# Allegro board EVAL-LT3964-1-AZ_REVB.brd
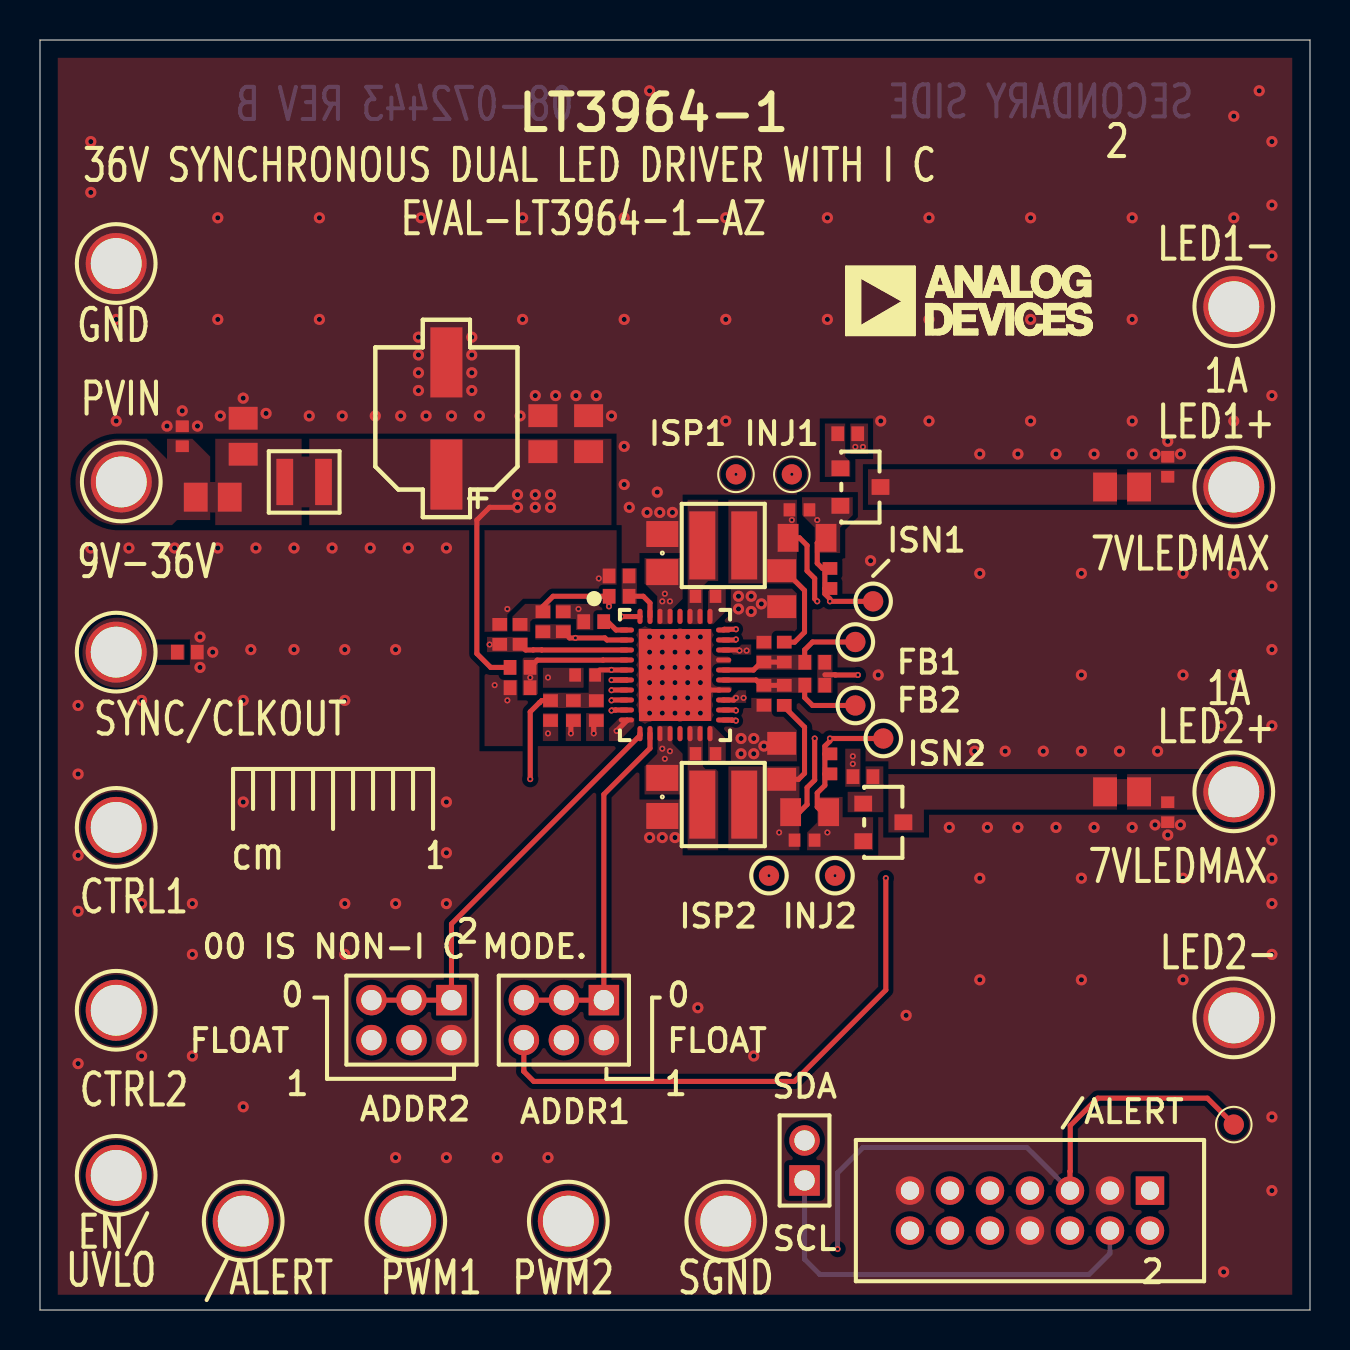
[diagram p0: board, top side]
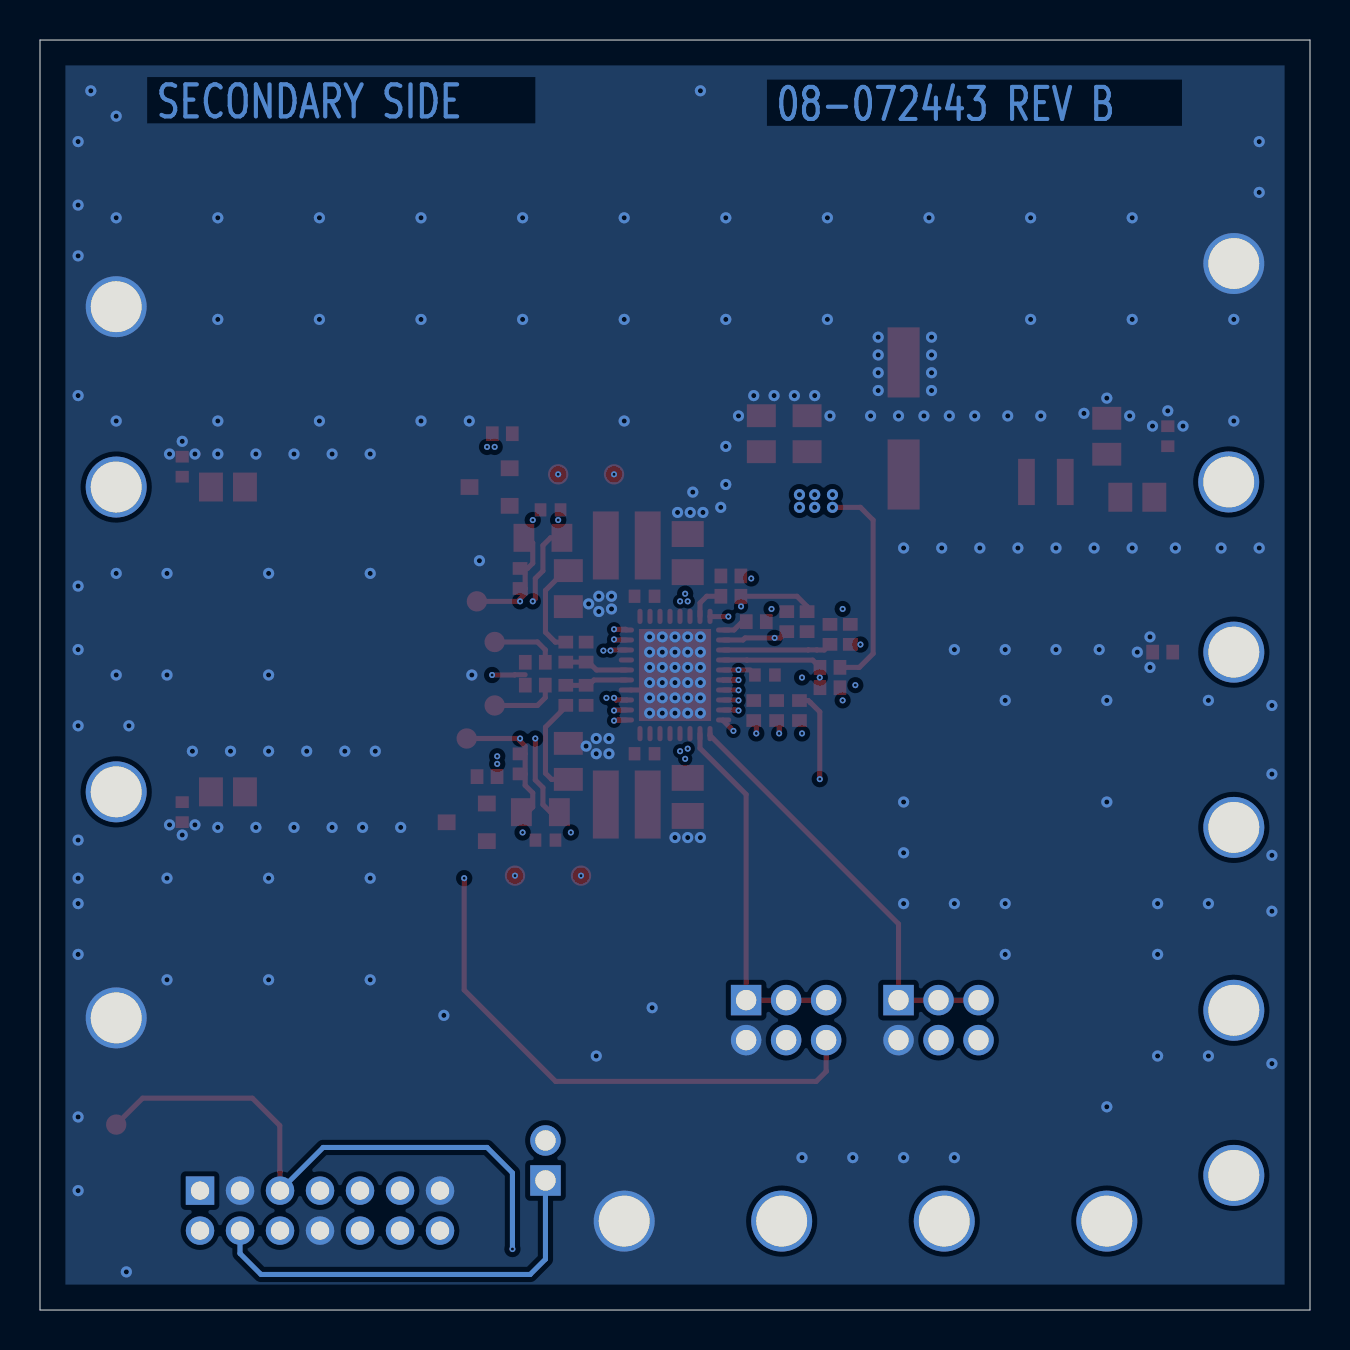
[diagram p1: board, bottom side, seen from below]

Outline 63.5 x 63.5 mm; copper layers: TOP, LAYER2, LAYER3, BOTTOM. Coordinates in mm from the lower left corner of the outline.
Outline path: 0,63.5 63.5,63.5 63.5,0 0,0 0,63.5

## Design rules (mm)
constraint set DEFAULT: min track width 0.254

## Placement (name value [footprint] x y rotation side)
C1  2.2uF  [C0805H60]  31.11 37.85 90 top
C2  TBD0402  [C0402]  37.97 40.01 0 top
C3  TBD0805  [C0805]  27.43 43.81 90 top
C4  TBD0805  [C0805]  25.15 43.81 90 top
C5  33UF  [CPLSMSQ260H303]  20.32 44.58 90 top
C6  2.2UF  [C0402]  27.25 31.75 180 top
C7  2.2uF  [C0805H60]  31.11 25.65 270 top
C8  TBD0402  [C0402]  38.23 23.49 0 top
C9  0.22uF  [C0402]  33.27 35.69 180 top
C10  2.2uF  [C0805]  37.08 36.07 270 top
C11  0.22uF  [C0402]  33.27 27.81 180 top
C12  2.2uF  [C0805]  37.08 27.43 90 top
C13  TBD0402  [C0402]  7.11 43.69 90 top
C14  TBD0805  [C0805]  10.16 43.69 90 top
C18  TBD0402  [C0402]  56.39 42.16 90 top
C19  TBD0402  [C0402]  56.39 24.89 270 top
E1  2501-2-00-80-00-00-07-0  [CNMILLMAX2501]  4.06 41.4 0 top
E2  2501-2-00-80-00-00-07-0  [CNMILLMAX2501]  3.81 52.32 0 top
E3  2501-2-00-80-00-00-07-0  [CNMILLMAX2501]  59.69 41.15 0 top
E4  2501-2-00-80-00-00-07-0  [CNMILLMAX2501]  59.69 50.16 0 top
E5  2501-2-00-80-00-00-07-0  [CNMILLMAX2501]  59.69 25.91 0 top
E6  2501-2-00-80-00-00-07-0  [CNMILLMAX2501]  59.69 14.61 0 top
E7  2501-2-00-80-00-00-07-0  [CNMILLMAX2501]  3.81 6.73 0 top
E8  2501-2-00-80-00-00-07-0  [CNMILLMAX2501]  3.81 24.13 0 top
E9  2501-2-00-80-00-00-07-0  [CNMILLMAX2501]  3.81 14.99 0 top
E10  2501-2-00-80-00-00-07-0  [CNMILLMAX2501]  10.16 4.45 0 top
E11  2501-2-00-80-00-00-07-0  [CNMILLMAX2501]  3.81 32.89 0 top
E12  2501-2-00-80-00-00-07-0  [CNMILLMAX2501]  18.29 4.45 0 top
E13  2501-2-00-80-00-00-07-0  [CNMILLMAX2501]  26.42 4.45 0 top
E14  2501-2-00-80-00-00-07-0  [CNMILLMAX2501]  34.29 4.45 0 top
FB1  100OHM  [L0805]  8.64 40.64 180 top
FB2  1500 OHMS  [L0805]  54.1 41.15 0 top
FB3  1500 OHMS  [L0805]  54.1 25.91 0 top
J1  87831-1420  [CNMOLEX87831-1420]  55.5 5.97 180 top
JP1  TMM-103-02-L-D  [CNTHMHDR2X3L236W155H225]  28.19 15.49 180 top
JP2  TMM-103-02-L-D  [CNTHMHDR2X3L236W155H225]  20.57 15.49 180 top
JP3  TMM-102-01-G-S  [CNHDR1X2H195]  38.23 6.48 90 top
L1  4.7UH  [LSMSQ118H79_A]  34.16 38.23 0 top
L2  4.7UH  [LSMSQ118H79_A]  34.16 25.27 0 top
L3  2.2UH  [LSML98W79H39]  13.21 41.4 0 top
M1  IRLML6401TRPBF  [SOT23-M3]  41.02 41.15 270 top
M2  IRLML6401TRPBF  [SOT23-M3]  42.16 24.38 270 top
NOREF  -  []  316.99 177.42 0 top
NOREF#2  -  []  -165.35 -246.38 0 top
NOREF#3  -  []  -165.35 -246.38 0 top
NOREF#4  -  []  321.44 105.79 0 top
NOREF#5  -  []  0.64 62.86 270 top
NOREF#6  -  []  32.26 75.95 0 top
NOREF#7  -  []  -41.2 219.96 0 top
NOREF#8  -  []  104.85 72.6 0 top
NOREF#9  -  []  62.86 0.64 90 top
NOREF#10  -  []  0 0 90 top
NOREF#11  -  []  0.64 0.64 0 top
NOREF#12  -  []  62.86 62.86 180 top
NOREF#13  -  []  -165.35 -246.38 0 top
NOREF#14  -  []  -162.05 -236.73 0 top
NOREF#15  -  []  0 63.5 0 top
NOREF#16  -  []  9.65 27.05 0 top
NOREF#17  -  []  41.4 69.98 0 top
R1  332K  [R0402]  24 32.13 0 top
R2  51.1K  [R0402]  24 31.11 0 top
R3  100K  [R0402]  25.53 29.97 270 top
R4  100K  [R0402]  25.15 34.42 90 top
R5  100K  [R0402]  24 33.78 90 top
R6  165K  [R0402]  28.96 35.69 180 top
R7  499K  [R0402]  28.96 36.7 0 top
R8  27.4K  [R0402]  27.69 34.42 0 top
R9  20K  [R0402]  7.37 32.89 180 top
R10  1MEG  [R0402]  37.21 32.89 270 top
R11  169K  [R0402]  36.2 32.89 90 top
R12  0.1  [R0805]  38.35 38.61 0 top
R13  TBD0402  [R0402]  39.5 36.58 90 top
R14  1MEG  [R0402]  37.21 30.73 90 top
R15  169K  [R0402]  36.2 30.73 270 top
R16  0.1  [R0805]  38.48 24.89 0 top
R17  TBD0402  [R0402]  39.5 27.3 270 top
R21  TBD0402  [R0402]  22.99 33.78 270 top
R22  TBD0402  [R0402]  26.16 34.42 270 top
R24  TBD0402  [R0402]  38.73 32.38 180 top
R25  TBD0402  [R0402]  38.73 31.24 180 top
R26  100K  [R0402]  26.67 29.97 270 top
R27  100K  [R0402]  27.81 29.97 270 top
R28  0  [R0402]  40.39 43.81 180 top
R29  0  [R0402]  41.15 26.67 0 top
TP1  TESTPAD  [TPSMC40]  42.16 28.57 0 top
TP2  TESTPAD  [TPSMC40]  59.69 9.27 0 top
TP5  TESTPAD  [TPSMC40]  40.77 33.4 0 top
TP6  TESTPAD  [TPSMC40]  37.59 41.78 0 top
TP7  TESTPAD  [TPSMC40]  41.66 35.43 0 top
TP8  TESTPAD  [TPSMC40]  34.8 41.78 0 top
TP9  TESTPAD  [TPSMC40]  36.45 21.72 0 top
TP10  TESTPAD  [TPSMC40]  39.75 21.72 0 top
TP11  TESTPAD  [TPSMC40]  40.77 30.23 0 top
U1  LT3964RUHE-1#PBF  [QFN36_5X6_PAD4_6X3_6-05-08-1876]  31.75 31.75 270 top

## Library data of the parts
C1 C7 = CAP: Tolerance: 10; User Part Number: UPN; alternate symbols: (C0805H60); part number: CAP_SM-2.2UF,50V,10,E016729,C0805H60; tolerance: 10
C2 C8 C13 C18 C19 = CAP: User Part Number: UPN; alternate symbols: (C0402); part number: CAP_SM-TBD0402,TBD0402,TBD0402,E000381,C0402
C3 C4 C14 = CAP: User Part Number: UPN; alternate symbols: (C0805); part number: CAP_SM-TBD0805,TBD0805,TBD0805,E000383,C0805
C5 = CAPP: User Part Number: UPN; Tolerance: 20; alternate symbols: (CPLSMSQ260H303); part number: CAPP_SM-33UF,50V,20,E058112,CPLSMSQ260H303; tolerance: 20
C6 = CAP: User Part Number: UPN; Tolerance: 10; alternate symbols: (C0402); part number: CAP_SM-2.2UF,25V,10,E044855,C0402; tolerance: 10
C9 C11 = CAP: User Part Number: UPN; Tolerance: 10; alternate symbols: (C0402); part number: CAP_SM-0.22UF,50V,10,E038241,C0402; tolerance: 10
C10 C12 = CAP: User Part Number: UPN; Tolerance: 10; alternate symbols: (C0805); part number: CAP_SM-2.2UF,10V,10,E010425,C0805; tolerance: 10
E1-E14 = CNTP1P: User Part Number: UPN; Tolerance: N/A; alternate symbols: (CNMILLMAX2501); part number: CNTP1P_TH-2501-2-00-80-00-00-07-0,E031108,CNMILLMAX2501; tolerance: N/A
FB1 = FERRITE: User Part Number: UPN; Tolerance: 25; alternate symbols: (L0805); part number: FERRITE_SM-100OHM,25,E012241,L0805; tolerance: 25
FB2 FB3 = FERRITE: User Part Number: UPN; Tolerance: 25; alternate symbols: (L0805); part number: FERRITE_SM-1500 OHMS,25,E008092,L0805; tolerance: 25
J1 = CN14P: Tolerance: N/A; User Part Number: UPN; alternate symbols: (CNMOLEX87831-1420); part number: CN14P_TH-87831-1420,E010086,CNMOLEX87831-1420; tolerance: N/A
JP1 JP2 = CN6P_ODD_EVEN: User Part Number: UPN; Tolerance: N/A; alternate symbols: (CNTHMHDR2X3L236W155H225); part number: CN6P_ODD_EVEN_TH-TMM-103-02-L-D,E043044,CNTHMHDR2X3L236W155H225; tolerance: N/A
JP3 = CN2P: Tolerance: N/A; User Part Number: UPN; alternate symbols: (CNHDR1X2H195); part number: CN2P_TH-TMM-102-01-G-S,E021460,CNHDR1X2H195; tolerance: N/A
L1 L2 = IND: User Part Number: UPN; Tolerance: 20; alternate symbols: (LSMSQ118H79_A); part number: IND_SM-4.7UH,20,E024887,LSMSQ118H79_A; tolerance: 20
L3 = IND: User Part Number: UPN; Tolerance: 20; alternate symbols: (LSML98W79H39); part number: IND_SM-2.2UH,20,E058020,LSML98W79H39; tolerance: 20
M1 M2 = TRANPMOSFET_V12: User Part Number: UPN; Tolerance: N/A; alternate symbols: (SOT23-M3); part number: TRANPMOSFET_V12_SM-IRLML6401TRPBF,E023655,SOT23-M3; tolerance: N/A
R1 = RES: User Part Number: UPN; Tolerance: 1; alternate symbols: (R0402); part number: RES_SM-332K,E003766,1/10W,1,R0402; tolerance: 1
R2 = RES: User Part Number: UPN; Tolerance: 0.1; alternate symbols: (R0402); part number: RES_SM-51.1K,E020550,1/16W,0.1,R0402; tolerance: 0.1
R3-R5 R26 R27 = RES: User Part Number: UPN; Tolerance: 1; alternate symbols: (R0402); part number: RES_SM-100K,E017855,1/16W,1,R0402; tolerance: 1
R6 = RES: User Part Number: UPN; Tolerance: 1; alternate symbols: (R0402); part number: RES_SM-165K,E026053,1/16W,1,R0402; tolerance: 1
R7 = RES: User Part Number: UPN; Tolerance: 1; alternate symbols: (R0402); part number: RES_SM-499K,E019889,1/10W,1,R0402; tolerance: 1
R8 = RES: User Part Number: UPN; Tolerance: 1; alternate symbols: (R0402); part number: RES_SM-27.4K,E021819,1/10W,1,R0402; tolerance: 1
R9 = RES: User Part Number: UPN; Tolerance: 1; alternate symbols: (R0402); part number: RES_SM-20K,E003791,1/10W,1,R0402; tolerance: 1
R10 R14 = RES: User Part Number: UPN; Tolerance: 1; alternate symbols: (R0402); part number: RES_SM-1MEG,E003749,1/10W,1,R0402; tolerance: 1
R11 R15 = RES: User Part Number: UPN; Tolerance: 1; alternate symbols: (R0402); part number: RES_SM-169K,E006751,1/10W,1,R0402; tolerance: 1
R12 R16 = RES: User Part Number: UPN; Tolerance: 1; alternate symbols: (R0805); part number: RES_SM-0.1,E031559,1/2W,1,R0805; tolerance: 1
R13 R17 R21 R22 R24 R25 = RES: User Part Number: UPN; alternate symbols: (R0402); part number: RES_SM-TBD0402,E004049,TBD0402,TBD0402,R0402
R28 R29 = RES: User Part Number: UPN; Tolerance: JUMPER; alternate symbols: (R0402); part number: RES_SM-0,E003438,1/10W,JUMPER,R0402; tolerance: JUMPER
TP1 TP2 TP5-TP11 = NCTESTPAD: Tolerance: N/A; User Part Number: UPN; alternate symbols: (TPSMC40); part number: NCTESTPAD_SM-TESTPAD,E019801,TPSMC40; tolerance: N/A
U1 = ADLT3964_1: Tolerance: N/A; User Part Number: UPN; alternate symbols: (QFN36_5X6_PAD4_6X3_6-05-08-1876); part number: ADLT3964_1_SM-LT3964RUHE-1#PBF,E058111,QFN36_5X6_PAD4_6X3_6-05-08-1876; tolerance: N/A

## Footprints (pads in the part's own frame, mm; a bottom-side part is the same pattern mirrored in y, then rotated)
C0402
  rect 0.584x0.66 smd: 1(-0.5,0) 2(0.5,0)
C0805
  rect 1.143x1.448 smd: 1(-0.9,0) 2(0.9,0)
C0805H60
  rect 1.295x1.6 smd: 1(-0.953,0) 2(0.953,0)
CNHDR1X2H195
  rect 1.524x1.524 hole 1.016: 1(0,0)
  round 1.524 hole 1.016: 2(1.999,0)
CNMILLMAX2501
  round 3.048 hole 2.54: 1(0,0)
CNMOLEX87831-1420
  rect 1.422x1.422 hole 0.914: 1(0,0)
  round 1.422 hole 0.914: 2(0,2) 3(2,0) 4(2,2) 5(4,0) 6(4,2) 7(6,0) 8(6,2) 9(8,0) 10(8,2) 11(10,0) 12(10,2) 13(12,0) 14(12,2)
CNTHMHDR2X3L236W155H225
  rect 1.524x1.524 hole 1.016: 1(0,0)
  round 1.524 hole 1.016: 2(0,2) 3(2,0) 4(2,2) 5(4,0) 6(4,2)
CPLSMSQ260H303
  rect 3.505x1.6 smd: N(2.803,0) P(-2.803,0)
L0805
  rect 1.194x1.448 smd: 1(-0.85,0) 2(0.85,0)
LSML98W79H39
  rect 0.838x2.311 smd: 1(-0.969,0) 2(0.969,0)
LSMSQ118H79_A
  rect 1.295x3.404 smd: 1(-1.048,0) 2(1.048,0)
QFN36_5X6_PAD4_6X3_6-05-08-1876
  oval 0.254x0.762 smd: 1(-2.25,-2.431) 2(-1.75,-2.431) 3(-1.25,-2.431) 4(-0.75,-2.431) 5(-0.25,-2.431) 6(0.25,-2.431) 7(0.75,-2.431) 8(1.25,-2.431) 9(1.75,-2.431) 10(2.25,-2.431) 19(2.25,2.431) 20(1.75,2.431) 21(1.25,2.431) 22(0.75,2.431) 23(0.25,2.431) 24(-0.25,2.431) 25(-0.75,2.431) 26(-1.25,2.431) 27(-1.75,2.431) 28(-2.25,2.431)
  oval 0.762x0.254 smd: 11(2.931,-1.75) 12(2.931,-1.25) 13(2.931,-0.75) 14(2.931,-0.25) 15(2.931,0.25) 16(2.931,0.75) 17(2.931,1.25) 18(2.931,1.75) 29(-2.931,1.75) 30(-2.931,1.25) 31(-2.931,0.75) 32(-2.931,0.25) 33(-2.931,-0.25) 34(-2.931,-0.75) 35(-2.931,-1.25) 36(-2.931,-1.75)
  rect 4.597x3.607 smd: 37(0,0)
R0402
  rect 0.635x0.737 smd: 1(-0.5,0) 2(0.5,0)
R0805
  rect 1.041x1.397 smd: 1(-0.95,0) 2(0.95,0)
SOT23-M3
  rect 0.787x0.889 smd: 1(-0.94,-1.003) 2(0.94,-1.003) 3(0,1.003)
TPSMC40
  round 1.016 smd: 1(0,0)

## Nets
GND_POWER: C1.2(N2) C3.2(N2) C4.2(N2) C5.N(N2) C6.2(N2) C7.2(N2) C10.2(N2) C12.2(N2) C13.2(N2) C14.2(N2) C18.2(N2) C19.2(N2) E2.1(N1) E4.1(N1) E6.1(N1) E14.1(N1) J1.3 J1.8 J1.13 JP1.2 JP2.2 R2.1 R7.1 R8.1 R9.1 R11.2(N2) R15.2(N2) R21.1 R22.1 U1.22 U1.25 U1.37
VIN: C1.1 C3.1 C4.1 C5.P C7.1 C13.1 C14.1 E1.1(N1) FB1.1 FB1.2(N2) L3.1 L3.2(N2) R1.1 U1.13 U1.14(VIN2_2) U1.33 U1.34
ALERT: E10.1(N1) J1.5 R3.2(N2) TP2.1(N1) U1.6
INTVCC: C6.1 JP1.6(N6) JP2.6(N6) R3.1 R4.2(N2) R5.2(N2) R6.2(N2) R24.1 R25.1 R26.1 R27.1 U1.5
SCL: J1.4 JP3.1 U1.10
SDA: J1.7 JP3.2(N2) U1.9
UNNAMED_3_ADLT39641_I220_ADDR1: JP1.1 JP1.3 JP1.5 U1.12
UNNAMED_3_ADLT39641_I220_ADDR2: JP2.1 JP2.3 JP2.5 U1.11
UNNAMED_3_ADLT39641_I220_BST1: C9.1 U1.29
UNNAMED_3_ADLT39641_I220_BST2: C11.1 U1.18
UNNAMED_3_ADLT39641_I220_FB1: R10.2(N2) R11.1 R24.2(N2) TP5.1(N1) U1.24
UNNAMED_3_ADLT39641_I220_FB2: R14.2(N2) R15.1 R25.2(N2) TP11.1(N1) U1.23
UNNAMED_3_ADLT39641_I220_ISN1: C2.2(N2) M1.2(S) R12.2(N2) R13.1 R13.2(N2) TP6.1(N1) TP7.1(N1) U1.27
UNNAMED_3_ADLT39641_I220_ISP1: C2.1 C10.1 L1.2(N2) R10.1 R12.1 TP8.1(N1) U1.28
UNNAMED_3_ADLT39641_I220_PWM2: E13.1(N1) R27.2(N2) U1.8
UNNAMED_3_ADLT39641_I220_PWMTG1: R28.1 U1.26
UNNAMED_3_ADLT39641_I220_PWMTG2: R29.1 U1.21
UNNAMED_3_ADLT39641_I220_RT: R8.2(N2) U1.1
UNNAMED_3_ADLT39641_I220_SW11: C9.2(N2) L1.1 U1.30 U1.31
UNNAMED_3_ADLT39641_I220_SW21: C11.2(N2) L2.1 U1.16 U1.17
UNNAMED_3_ADLT39641_I220_TSET: R6.1 R7.2(N2) U1.35
UNNAMED_3_CAP_I157_N1: C18.1 E3.1(N1) FB2.1 FB2.2(N2) M1.3
UNNAMED_3_CAP_I172_N1: C19.1 E5.1(N1) FB3.1 FB3.2(N2) M2.3
UNNAMED_3_CAP_I178_N1: C8.1 C12.1 L2.2(N2) R14.1 R16.1 TP9.1(N1) U1.19
UNNAMED_3_CAP_I178_N2: C8.2(N2) M2.2(S) R16.2(N2) R17.1 R17.2(N2) TP1.1(N1) TP10.1(N1) U1.20
UNNAMED_3_CNTP1P_I106_N1: E7.1(N1) R1.2(N2) R2.2(N2) U1.4
UNNAMED_3_CNTP1P_I107_N1: E8.1(N1) R4.1 R22.2(N2) U1.2
UNNAMED_3_CNTP1P_I108_N1: E9.1(N1) R5.1 R21.2(N2) U1.3
UNNAMED_3_CNTP1P_I124_N1: E11.1(N1) R9.2(N2) U1.36
UNNAMED_3_CNTP1P_I125_N1: E12.1(N1) R26.2(N2) U1.7
UNNAMED_3_RES_I210_N2: M1.1 R28.2(N2)
UNNAMED_3_RES_I215_N2: M2.1 R29.2(N2)

Pads without a net: J1 1 2 6 9 10 11 12 14; JP1 4; JP2 4; U1 15 32

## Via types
v1: diameter 0.305, hole 0.152, TOP to BOTTOM, 54 vias
v2: diameter 0.559, hole 0.254, TOP to BOTTOM, 214 vias

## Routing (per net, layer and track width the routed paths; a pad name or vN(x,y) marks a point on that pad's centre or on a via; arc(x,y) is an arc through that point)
GND_POWER: length 2.4
  TOP w0.254: v2(33.02,30.61) 33.02,31 33.96,31 ; v2(33.02,33.66) 33.08,33.66 33.08,32.66
  vias: v1(22.73,31.24) v1(23.37,35.05) v1(23.37,30.48) v1(25.4,31.62) v1(26.92,35.05) v1(27.94,36.58) v2(1.91,30.23) v2(1.91,26.8) v2(1.91,22.73) v2(1.91,19.94) v2(1.91,12.32) v2(2.54,58.42) v2(2.54,55.88) v2(2.54,38.1) v2(3.81,49.53) v2(3.81,44.45) v2(4.45,38.1) v2(5.08,30.48) v2(5.08,20.32) v2(5.08,12.7) v2(6.35,44.2) v2(6.73,38.1) v2(7.11,44.96) v2(7.62,20.32) v2(7.62,17.78) v2(7.62,12.7) v2(7.87,44.2) v2(8,33.66) v2(8,32.13) v2(8.64,32.89) v2(8.89,54.61) v2(8.89,49.53) v2(8.89,38.1) v2(9.02,44.7) v2(10.16,45.59) v2(10.16,30.48) v2(10.16,25.4) v2(10.16,10.16) v2(10.54,33.02) v2(10.8,38.1) v2(11.3,44.83) v2(12.7,38.1) v2(12.7,33.02) v2(13.46,44.7) v2(13.97,54.61) v2(13.97,49.53) v2(14.61,38.1) v2(15.11,44.7) v2(15.24,33.02) v2(15.24,30.48) v2(15.24,20.32) v2(15.24,17.78) v2(16.51,38.1) v2(16.76,44.7) v2(17.78,33.02) v2(17.78,20.32) v2(17.78,7.62) v2(18.03,44.7) v2(18.41,38.1) v2(18.92,48.64) v2(18.92,47.75) v2(18.92,46.86) v2(18.92,45.97) v2(19.05,54.61) v2(19.3,44.7) v2(20.32,38.1) v2(20.32,25.4) v2(20.32,22.86) v2(20.32,20.32) v2(20.32,7.62) v2(20.57,44.7) v2(21.59,48.64) v2(21.59,47.75) v2(21.59,46.86) v2(21.59,45.97) v2(21.97,44.7) v2(22.86,7.62) v2(24,44.7) v2(24.13,54.61) v2(24.13,49.53) v2(24.77,45.72) v2(25.4,7.62) v2(25.78,45.72) v2(26.8,45.72) v2(27.81,45.72) v2(28.57,44.7) v2(29.21,54.61) v2(29.21,49.53) v2(29.21,43.18) v2(29.21,41.27) v2(29.46,40.13) v2(30.35,39.88) v2(30.48,60.96) v2(30.48,33.66) v2(30.48,32.89) v2(30.48,32.13) v2(30.48,31.37) v2(30.48,30.61) v2(30.48,29.84) v2(30.48,23.62) v2(30.86,40.89) v2(30.99,39.88) v2(31.11,33.66) v2(31.11,32.89) v2(31.11,32.13) v2(31.11,31.37) v2(31.11,30.61) v2(31.11,29.84) v2(31.11,23.62) v2(31.62,39.88) v2(31.75,33.66) v2(31.75,32.89) v2(31.75,32.13) v2(31.75,31.37) v2(31.75,30.61) v2(31.75,29.84) v2(31.75,23.62) v2(32.38,33.66) v2(32.38,32.89) v2(32.38,32.13) v2(32.38,31.37) v2(32.38,30.61) v2(32.38,29.84) v2(32.89,15.11) v2(33.02,32.89) v2(33.02,32.13) v2(33.02,31.37) v2(33.02,29.84) v2(34.29,54.61) v2(34.29,49.53) v2(34.29,44.45) v2(34.92,35.69) v2(34.92,35.05) v2(35.05,28.57) v2(35.05,27.81) v2(35.56,35.69) v2(35.56,34.92) v2(35.69,28.57) v2(35.69,27.81) v2(35.69,12.7) v2(36.07,35.31) v2(36.2,28.19) v2(39.37,54.61) v2(39.37,49.53) v2(41.53,37.47) v2(41.91,31.75) v2(42.04,44.45) v2(43.31,14.73) v2(44.45,54.61) v2(44.45,49.53) v2(44.45,44.45) v2(45.47,24.13) v2(46.74,27.94) v2(46.99,42.8) v2(46.99,36.83) v2(46.99,21.59) v2(46.99,16.51) v2(47.37,24.13) v2(48.26,27.94) v2(48.89,42.8) v2(48.89,24.13) v2(49.53,54.61) v2(49.53,49.53) v2(49.53,44.45) v2(50.16,27.94) v2(50.8,42.8) v2(50.8,24.13) v2(52.07,36.83) v2(52.07,31.75) v2(52.07,27.94) v2(52.07,21.59) v2(52.07,16.51) v2(52.7,42.8) v2(52.7,24.13) v2(53.98,27.94) v2(54.61,54.61) v2(54.61,49.53) v2(54.61,44.45) v2(54.61,42.8) v2(54.61,24.13) v2(55.75,42.8) v2(55.75,24.26) v2(55.88,27.94) v2(56.39,43.43) v2(56.39,23.75) v2(57.02,42.8) v2(57.02,24.26) v2(57.15,36.83) v2(57.15,31.75) v2(57.15,21.59) v2(57.15,16.51) v2(59.05,29.21) v2(59.18,1.91) v2(59.69,59.69) v2(59.69,54.61) v2(59.69,44.45) v2(59.69,36.83) v2(59.69,31.75) v2(60.96,60.96) v2(61.59,58.42) v2(61.59,55.25) v2(61.59,52.7) v2(61.59,45.72) v2(61.59,36.2) v2(61.59,33.02) v2(61.59,29.21) v2(61.59,23.49) v2(61.59,21.59) v2(61.59,20.32) v2(61.59,17.78) v2(61.59,9.65) v2(61.59,5.97)
VIN: length 10.9
  TOP w0.254: R1.1 22.53,32.13 21.84,32.82 21.84,39.5 22.48,40.13 v2(23.88,40.13)
  vias: v1(31.11,35.43) v1(31.11,28.07) v1(31.24,35.81) v1(31.24,27.56) v1(31.5,35.43) v1(31.5,27.94) v2(23.88,40.77) v2(24.77,40.77) v2(24.77,40.13) v2(25.53,40.77) v2(25.53,40.13)
ALERT: length 100.2
  TOP w0.254: U1.6 28.58,31.5 v1(28.57,31.5) 29.35,31.5 29.35,31.5 ; TP2.1 58.37,10.59 52.88,10.59 51.51,9.22 51.51,6.95 51.5,6.93 J1.5
  LAYER3 w0.254: v1(39.88,3.05) 38.61,1.78 12.83,1.78 E10.1 13.97,8.25 13.97,20.95 21.46,28.45 25.02,28.45 v1(25.4,28.83) 25.4,30.35 26.54,31.5 v1(28.57,31.5)
  BOTTOM w0.254: v1(39.88,3.05) 39.88,6.86 41.15,8.13 49.34,8.13 J1.5
INTVCC: length 77.7
  TOP w0.254: v1(28.45,35.18) 28.45,35.68 R6.2 25.65,35.69 25.15,35.18 R4.2 ; R3.1 25.09,30.47 24.98,30.37 24.97,30.37 24.51,29.91 v1(24.51,26.54) ; v1(40.89,31.75) 39.77,31.75 39.76,31.76 39.24,31.76 ; v1(42.29,21.59) 42.29,16 37.72,11.43 24.69,11.43 24.18,11.94 24.19,11.95 JP1.6 ; 27.99,32 v1(28.57,32) 28.58,32 U1.5
  LAYER3 w0.254: v1(42.29,21.59) 42.29,30.35 v1(40.89,31.75) ; 22.73,13.49 JP1.6 ; 22.73,13.49 22.45,13.78 22.45,18.76 24.51,20.83 v1(24.51,26.54) ; 22.73,13.49 22.73,13.08 21.08,11.43 17.14,11.43 16.57,12 JP2.6 ; v1(28.45,35.18) 28.57,35.05 v1(28.57,32)
SCL: length 73.5
  TOP w0.254: v1(28.83,28.96) 29.35,29.48 29.35,29.5
  LAYER3 w0.254: J1.4 53.5,3 54.22,2.29 56.64,2.29 57.4,3.05 57.4,8.51 55.37,10.54 44.96,10.54 39.72,15.78 35.78,15.78 28.83,22.73 v1(28.83,28.96)
  BOTTOM w0.254: JP3.1 38.23,2.54 38.99,1.78 52.45,1.78 53.5,2.83 J1.4
SDA: length 42.5
  TOP w0.254: U1.9 28.78,30 28.78,30 28.6,30 v1(28.57,29.97)
  LAYER3 w0.254: 41.08,9.84 41.66,9.27 47.37,9.27 49.5,7.14 J1.7 ; 41.08,9.84 41.08,13.14 38.96,15.27 35.57,15.27 28.19,22.65 28.19,29.59 v1(28.57,29.97) ; 41.08,9.84 40.51,9.27 39.02,9.27 JP3.2
UNNAMED_3_ADLT39641_I220_ADDR1: length 18.3
  TOP w0.254: U1.12 30.5,28.09 28.19,25.78 JP1.1 JP1.3 JP1.5 24.18,15.49
UNNAMED_3_ADLT39641_I220_ADDR2: length 21.2
  TOP w0.254: JP2.5 JP2.3 JP2.1 20.57,19.3 30,28.73 U1.11
UNNAMED_3_ADLT39641_I220_FB1: length 6.4
  TOP w0.254: R24.2 38.23,33.01 38.63,33.4 TP5.1 ; 37.08,32.39 R11.1 36.07,32.39 35.68,32 U1.24
UNNAMED_3_ADLT39641_I220_FB2: length 6.3
  TOP w0.254: 37.08,31.23 R15.1 36.07,31.23 35.8,31.5 U1.23 ; TP11.1 38.63,30.23 38.23,30.62 R25.2
UNNAMED_3_ADLT39641_I220_ISN1: length 18.1
  TOP w0.254: U1.27 34.77,33.5 v1(34.8,33.53) ; 39.24,37.08 39.12,37.08 38.86,37.34 38.86,38.35 39.12,38.61 R12.2 39.43,38.61 ; 39.24,37.08 39.49,37.08 R13.2 39.25,37.08 39.24,37.08 ; 39.24,37.08 39.24,36.07 ; 39.24,36.07 39.25,36.08 R13.1 ; 39.24,36.07 39.24,35.81 39.5,35.55 v1(39.5,35.43) TP7.1
  LAYER3 w0.254: v1(34.8,33.53) 35.06,33.53 35.09,33.55 36.04,33.55 36.07,33.53 38.73,33.53 39.4,34.19 39.4,35.34 v1(39.5,35.43) ; v1(38.86,39.5) 38.33,40.03 37.31,40.03 36.7,40.64 36.7,41.4 37.08,41.78 v1(37.59,41.78)
UNNAMED_3_ADLT39641_I220_ISP1: length 19.1
  TOP w0.254: U1.28 34.22,34.04 v1(34.8,34.04) ; v1(38.86,35.43) 38.73,35.56 38.73,36.58 38.35,36.96 38.35,38.23 37.97,38.61 37.53,38.61 ; C10.1 37.24,36.97 38.23,35.98 38.23,33.89 37.73,33.39 R10.1
  LAYER3 w0.254: v1(38.86,35.43) 38.86,34.42 38.48,34.04 v1(34.8,34.04) ; v1(37.59,39.5) 36.96,39.5 36.2,40.26 36.2,41.4 35.81,41.78 v1(34.8,41.78)
UNNAMED_3_ADLT39641_I220_PWM2: length 32.9
  TOP w0.254: v1(28.57,30.48) 28.6,30.5 U1.8 ; v1(27.69,28.83) 27.69,29.4
  LAYER3 w0.254: E13.1 31.75,9.78 31.75,17.14 27.18,21.72 27.18,28.83 ; v1(28.57,30.48) 27.94,30.48 27.18,29.72 27.18,28.83 ; 27.18,28.83 v1(27.69,28.83)
UNNAMED_3_ADLT39641_I220_PWMTG1: length 17.5
  TOP w0.254: U1.26 34.95,33 v1(34.98,32.97)
  LAYER3 w0.381: v1(34.98,32.97) v1(35.33,32.97)
  LAYER3 w0.508: v1(35.33,32.97) 35.71,32.97 36.36,32.32 39.75,32.32 40.26,32.83 40.26,42.65 v1(40.77,43.15) v1(41.15,43.15)
UNNAMED_3_ADLT39641_I220_PWMTG2: length 9.9
  TOP w0.254: 34.15,30.5 U1.21 34.69,30.5 v1(34.8,30.61)
  LAYER3 w0.254: 35.18,31.11 34.8,30.73 v1(34.8,30.61)
  LAYER3 w0.508: 35.18,31.11 39.38,31.11 40.26,30.24 40.26,28.07 v1(40.64,27.69) v1(40.64,27.3)
  vias: v1(35.18,30.61)
UNNAMED_3_ADLT39641_I220_RT: length 1.3
  TOP w0.254: U1.1 28.8,34 28.38,34.42 R8.2
UNNAMED_3_ADLT39641_I220_TSET: length 1.9
  TOP w0.254: U1.35 30.5,35.35 30.16,35.69 R6.1
UNNAMED_3_CAP_I178_N1: length 18.9
  TOP w0.254: R14.1 37.21,30.16 38.23,29.14 38.23,26.84 37.92,26.53 C12.1 ; v1(34.8,29.46) 34.77,29.49 34.6,29.49 34.59,29.5 U1.19 ; v1(38.73,28.57) 38.73,26.5 38.35,26.12 38.35,25.27 37.97,24.89 R16.1
  LAYER3 w0.254: v1(38.73,28.57) 38.73,29.21 38.48,29.46 v1(34.8,29.46) ; v1(36.45,21.72) 37.47,21.72 37.85,22.1 37.85,23.62 37.59,23.88 v1(36.96,23.88)
UNNAMED_3_CAP_I178_N2: length 18.1
  TOP w0.254: 39.24,26.8 39.24,27.81 ; 39.24,26.8 39.25,26.8 R17.2 ; 39.24,26.8 39.24,26.23 38.86,25.85 38.86,25.15 39.12,24.89 R16.2 ; 39.24,27.81 39.24,28.19 39.5,28.45 v1(39.5,28.57) TP1.1 ; 39.24,27.81 39.25,27.81 R17.1 ; v1(34.8,29.97) 34.77,30 U1.20
  LAYER3 w0.254: v1(39.75,21.72) 38.73,21.72 38.35,22.1 38.35,23.62 38.61,23.88 v1(39.37,23.88) ; v1(39.5,28.57) 39.4,28.57 39.27,28.7 39.27,29.44 38.73,29.97 v1(34.8,29.97)
UNNAMED_3_CNTP1P_I106_N1: length 40.2
  TOP w0.254: R1.2 24.86,32.49 28.15,32.49 28.16,32.5 U1.4
  LAYER3 w0.254: E7.1 12.32,15.24 12.32,20.83 20.83,29.34 23.88,29.34 24.51,29.97 v1(24.51,31.62)
UNNAMED_3_CNTP1P_I107_N1: length 30.6
  TOP w0.254: U1.2 28.35,33.5 28.24,33.6 v1(26.77,33.6) 26.47,33.6 R22.2
  LAYER3 w0.254: v1(26.77,33.6) 26.34,34.04 22.23,34.04 12.32,24.13 E8.1
UNNAMED_3_CNTP1P_I108_N1: length 33.6
  TOP w0.254: R5.1 24.28,33 24.65,33 24.66,33.01 25.08,33.01 25.09,33 U1.3
  LAYER3 w0.254: v1(22.48,33.27) 22.48,32.51 10.54,20.57 10.54,18.03 7.49,14.99 E9.1
UNNAMED_3_CNTP1P_I124_N1: length 28.4
  TOP w0.254: 29.08,34.65 v1(29.08,34.67) 29.99,34.67 U1.36
  LAYER3 w0.254: v1(29.08,34.67) 29.08,35.56 28.83,35.81 6.73,35.81 E11.1
UNNAMED_3_CNTP1P_I125_N1: length 40.3
  TOP w0.254: U1.7 28.59,31 v1(28.57,30.99) ; v1(26.54,28.83) 26.54,29.27 26.67,29.4
  LAYER3 w0.254: E12.1 18.29,6.86 20.45,9.02 28.02,9.02 30.05,11.05 30.05,16.81 26.54,20.32 v1(26.54,28.83) 26.54,30.23 27.3,30.99 v1(28.57,30.99)

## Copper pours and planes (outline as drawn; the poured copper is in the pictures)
GND_POWER on TOP: 62.61,62.61 0.89,62.61 0.89,0.76 62.61,0.76 ; 1 cut-out
GND_POWER on BOTTOM: 1.27,1.27 62.23,1.27 62.23,62.23 1.27,62.23 ; 6 cut-outs
GND_POWER on LAYER2: 1.14,1.27 62.1,1.27 62.1,62.23 1.14,62.23
GND_POWER on LAYER3: 62.23,62.23 1.27,62.23 1.27,1.27 62.23,1.27 ; 6 cut-outs
VIN on TOP: 30.86,29.21 30.86,27.81 30.23,27.18 30.23,25.78 32.13,25.78 32.13,27.81 31.62,28.32 31.62,29.21
VIN on TOP: 32.13,37.59 30.23,37.59 30.23,36.32 30.86,35.69 30.86,34.29 31.62,34.29 31.62,35.05 32.13,35.56
VIN on LAYER3: 32,35.05 30.73,35.05 29.97,34.29 29.97,29.21 30.48,28.7 31.88,28.7 31.88,26.67 30.1,26.67 28.96,27.81 28.96,36.7 26.29,39.37 23.24,39.37 23.24,41.53 26.67,41.53 31.5,36.7 32,36.7
ALERT on TOP: 25.15,29.84 25.91,29.84 25.91,28.45 25.15,28.45
INTVCC on TOP: 24.26,35.31 25.53,35.31 25.53,34.54 24.64,34.54 24.51,34.42 24.51,33.91 23.62,33.91 23.62,34.67
INTVCC on TOP: 38.86,32.77 38.86,30.86 39.62,30.86 39.62,32.77
INTVCC on TOP: 27.43,32.13 28.19,32.13 28.19,30.1 25.15,30.1 25.15,30.86 27.43,30.86
SCL on TOP: 28.45,29.08 28.96,29.59 29.72,29.59 29.72,29.21 28.96,28.45 28.45,28.45
UNNAMED_3_ADLT39641_I220_BST1 on TOP: 33.4,34.29 33.66,34.29 34.29,34.92 34.29,36.07 33.53,36.07 33.4,35.94
UNNAMED_3_ADLT39641_I220_BST2 on TOP: 33.4,29.21 33.66,29.21 34.29,28.57 34.29,27.43 33.4,27.43
UNNAMED_3_ADLT39641_I220_FB1 on TOP: 35.81,32.77 35.81,32 38.61,32 38.61,32.77
UNNAMED_3_ADLT39641_I220_FB2 on TOP: 35.81,31.62 35.81,30.86 38.61,30.86 38.61,31.62
UNNAMED_3_ADLT39641_I220_ISN1 on TOP: 38.1,40.64 40.64,40.64 40.64,39.75 40.01,39.12 40.01,37.85 38.73,37.85 38.73,39.12 38.1,39.75
UNNAMED_3_ADLT39641_I220_ISP1 on TOP: 37.85,40.51 37.85,36.32 34.42,36.32 34.42,40.51
UNNAMED_3_ADLT39641_I220_PWM2 on TOP: 27.3,29.84 28.19,29.84 28.19,28.45 27.3,28.45
UNNAMED_3_ADLT39641_I220_PWMTG1 on TOP: 41.4,42.8 40.51,42.8 40.51,44.32 41.4,44.32
UNNAMED_3_ADLT39641_I220_PWMTG2 on TOP: 40.26,28.07 41.02,28.07 41.02,26.16 40.26,26.16
UNNAMED_3_ADLT39641_I220_SW11 on TOP: 32.38,34.29 32.38,40.51 33.91,40.51 33.91,36.45 33.4,36.45 33.15,36.2 33.15,34.29
UNNAMED_3_ADLT39641_I220_SW21 on TOP: 32.38,29.21 32.38,22.99 33.91,22.99 33.91,26.92 33.78,27.05 33.27,27.05 33.15,27.18 33.15,29.21
UNNAMED_3_ADLT39641_I220_TSET on TOP: 29.08,37.08 29.08,35.31 29.84,35.31 29.84,37.08
UNNAMED_3_CAP_I157_N1 on TOP: 41.4,42.04 60.2,42.04 60.2,40.26 41.4,40.26
UNNAMED_3_CAP_I172_N1 on TOP: 42.42,23.88 42.42,26.8 60.2,26.8 60.2,25.02 44.2,25.02 44.2,23.88
UNNAMED_3_CAP_I178_N1 on TOP: 34.42,27.18 37.97,27.18 37.97,22.99 34.42,22.99
UNNAMED_3_CAP_I178_N2 on TOP: 40.13,24.64 41.66,24.64 41.66,22.99 38.35,22.99 38.35,23.88 38.86,24.38 38.86,25.65 40.13,25.65
UNNAMED_3_CNTP1P_I106_N1 on TOP: 24.13,32.64 24.13,30.73 24.89,30.73 24.89,32.64
UNNAMED_3_CNTP1P_I107_N1 on TOP: 24.77,34.29 26.54,34.29 26.54,33.53 24.77,33.53
UNNAMED_3_CNTP1P_I108_N1 on TOP: 22.35,33.66 24.38,33.66 24.38,32.89 22.35,32.89
UNNAMED_3_CNTP1P_I125_N1 on TOP: 26.29,29.84 27.05,29.84 27.05,28.45 26.29,28.45
UNNAMED_3_RES_I210_N2 on TOP: 39.24,44.32 40.26,44.32 40.26,42.67 40.51,42.42 40.51,41.66 39.24,41.66
UNNAMED_3_RES_I215_N2 on TOP: 41.27,27.18 42.16,27.18 42.16,24.89 40.39,24.89 40.39,25.91 41.27,25.91

Small or netless copper shapes (teardrops, artwork), in the pictures only: 4 on TOP

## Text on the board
BOTTOM: 08-072443 REV B | SECONDARY SIDE
User.Comments: 4.    INSTALL SHUNTS AS SHOWN ON ASSEMBLY DRAWING. | 6.   TEST POINTS SHOULD BE FREE OF SOLDER. | 7.   INSTALL THE FOLLOWING SHUNS. | JP1: PIN3 & PIN4. | JP2: PIN3 & PIN4. | PCB : BOTTOM | PCB : TOP | TURRETS
Ref Des/Silkscreen Top: FLOAT | 00 IS NON-I C MODE. | 0 | 1 | ADDR2 | 2 | ADDR1 | ISP1 | ISP2 | INJ1 | SDA | SCL | INJ2 | ISN1 | FB1 | FB2 | ISN2 | /ALERT | 36V SYNCHRONOUS DUAL LED DRIVER WITH I C | EVAL-LT3964-1-AZ | UVLO | GND | EN/ | PVIN | CTRL1 | CTRL2 | 9V-36V | SYNC/CLKOUT | PWM1 | PWM2 | SGND | 7VLEDMAX | LED1- | LED1+ | LED2+ | LED2- | 1A | LT3964-1
PAGE_OUTLINE: 2 | LED DRIVER WITH I C | 36V SYNCHRONOUS DUAL
DISPLAY_TOP: FAB NOTES REVISION: 2ND NOVEMBER 2022 | 8.   IMPEDANCE REQUIREMENTS: IF NO STACKUP IS DEFINED, THE VENDOR IS ALLOWED TO ADJUST THE DIELECTRIC | 13.  PLATING SPECIFICATION: | 1.   DIMENSIONS ARE IN INCHES (EXCEPT WHERE NOTED). | ALL DOCUMENTS & SPECIFICATIONS REFERRED TO BELOW SHOULD BE THE LATEST REVISIONS. | 2.  BOARD MATERIAL:(USE CHECKED ITEMS) | 3.   ALL LAMINATES & BONDING MATERIALS SHOULD BE SELECTED FROM IPC-4101 OR IPC-4103,(TG>170 DEGC TD>300 DEGC) | 4.   REFER TO IPC-6010 SERIES, CLASS 2 FOR FABRICATION. | 5.   REFER TO LAMINATION DIAGRAM FOR OVERALL BOARD THICKNESS, TOLERANCE APPLIES AFTER ALL LAMINATION AND PLATING | 6.   BOW & TWIST NOT TO EXCEED 0.0075 INCHES (0.75%) PER LINEAR INCH AND SHOULD BE MEASURED PER IPC-TM-650, METHOD 2.4.22. | 7.   ACCEPTABILITY PER ADI SPECIFICATION TST00115. | 9.   FILLET OPTIONS TO ENHANCE RELIABILITY AT PAD JUNCTIONS WHERE SPACING PERMITS. | 10.  THIEVING: | 11.  LAYER TO LAYER REGISTRATION SHALL BE WITHIN 0.003 INCHES. | 12.  DRILL SIZES ARE FINISHED HOLE SIZES. ALL HOLES SHALL BE LOCATED WITHIN 0.005 INCHES DTP,UNLESS SPECIFIED. | 14.  SURFACE FINISH: | 15.  SOLDERMASK: | 16.  APPLY SILKSCREEN TO BOTH SIDES USING A NON-CONDUCTIVE, EPOXY BASED INK PER ARTWORK. | (X) WHITE | ( ) OTHER | PROCESSES. FINISHED THICKNESS MEASURED FROM TOP COPPER TO BOTTOM COPPER. | (X)  ISOLA 370HR OR S1000-2 OR IT180 OR EQUIVALENT | ( )  ISOLA-FR408HR OR EQUIVALENT | ( )  ISOLA IS410 | ( )  MEGTRON 6 | ( )  NELCO-4000-13 | ( )  ROGERS 4350B | ( ) ROGERS 3003 | ( ) ARLON 85N | ( ) EM370D | ( )  OTHER ________________________ | ( ) FILLETS ALLOWED | (X) FILLETS NOT ALLOWED | ( ) VENDOR MAY ADD THIEVING TO COMPENSATE FOR LOW COPPER DENSITY AREAS MAINTAINING A MINIMUM | ( ) VENDOR MAY NOT ADD THIEVING TO COMPENSATE FOR LOW COPPER DENSITY AREAS. | (X) LPI | ( ) OTHER_________ | COLOR | (X) GREEN | HINDER PROPER SOLDER WICKING. BARREL RELIEF ON SOLDERMASK ALLOWED IN UNFILLED VIA IN PAD HOLES. | (X) REFER TO LAMINATION DIAGRAM FOR FINISHED COPPER WEIGHT/THICKNESS REQUIRMENTS | (X) IMMERSION GOLD (ENIG) 1.58-3.94 MICRO INCHES OVER 118-236 MICRO INCHES MIN. OF ELECTROLESS NICKEL PER IPC-4552 | ( ) OSP (ORGANIC SOLDERABILITY PRESERVATIVE) | ( ) IMMERSION SILVER | ( ) SOFT WIRE BONDABLE GOLD 30-50 MICRO INCHES OF SOFT WIRE | ( ) EDGE CONNECTOR FINGERS ARE TO BE PLATED WITH 100 MICRO-INCHES(.0001") OF LOW STRESS | THICKNESS & TRACE WIDTHS TO MEET THE IMPEDANCE REQUIREMENT. IF SPECIFIED, THE VENDOR MUST | TRACE WIDTH & SPACING THAT IMPACT THE REQUIREMENTS MUST HAVE WRITTEN APPROVAL FROM ADI. | MINIMUM BARREL PLATING OF 0.001 INCHES. PLATED HOLES SHALL NOT BE ROUGH OR IRREGULAR SO AS TO | SOLDERMASK OVER BARE COPPER OR BARE GOLD (BOTH SIDES) TO MEET IPC-SM-840. | IF PRESENT,DO NOT MODIFY SOLDERMASK DEFINED PADS (MASK OPENINGS LESS THAN COPPER PAD) WITHOUT APPROVAL. | MEET THE REQUIREMENTS LISTED IN THE IMPEDANCE TABLE. ANY ADJUSTMENT MADE TO THE DEFINED STACKUP, | UL FLAMMABILITY RATING 94V-0. BOARD MATERIAL & CONSTRUCTION SHALL MEET THE REQUIREMENTS OF UL796/UL796F. | BONDABLE GOLD OVER 100-150 MICRO INCHES OF NICKEL | NICKEL UNDER 30 MICRO-INCHES (.0003') OF GOLD | 0.100 INCH CLEARANCE FROM ALL COPPER FEATURES, | THE STARTING COPPER WEIGHT/THICKNESS CAN VARY AS LONG AS THE FINISHED COPPER | WEIGHT/THICKNESS IS NOT LESS THAN THE SPECIFIED VALUE. | UNLESS OTHERWISE SPECIFIED | HOMOGENOUS MATERIALS IN THIS BOARD SHALL BE COMPLAINT WITH THE EU DIRECTIVE 2002/95/EC | WORKMANSHIP SHALL CONFORM TO IPC-A-600, CLASS 2. | 21.  INTENTIONAL SHORTS: | 17.  FINAL ELECTRICAL TEST TO BE PERFORMED USING PROVIDED IPC-D-356A NETLIST OR ODB++ FORMAT FILE. | 22.  PEMNUTS: | 23.  MANUFACTURER TO ETCH/STAMP WITH PERMANENT NON-CONDUCTIVE INK | ON SECONDARY SIDE UNLESS OTHERWISE SPECIFIED: | 18.  A TIME DOMAIN REFLECTOMETER REPORT (TDR) FOR EACH IMPEDANCE CONTROLLED LAYER & A CERTIFICATE | 19.  IF PRESENT, ALL BLIND/BURIED VIAS WITH AN ASPECT RATIO <1:1 TO BE PLATED SHUT WITH COPPER WHEN | 20.  FOR VIA FILL INFORMATION REFER TO DRILL CHART: | 25. PANELIZATION: | 27.  MINIMUM DESIGN LINE WIDTH IS .008 INCH. | 28.  MINIMUM DESIGN LINE SPACING IS .008 INCH. | IS ACCEPTABLE, ALL OTHER INSTANCES MUST BE REPORTED. | IF AN INTENTIONAL SHORT REPORT IS SUPPLIED AND DOES NOT MATCH THE FAB DATA THEN | THE PCB SHALL HAVE A VERIFICATION STAMP. | (x)  NON-CONDUCTIVE EPOXY FILL ALL LESS THAN  0.012 INCHES DRILLED VIAS | ( )  COPPER FILL ALL 0.XXXX INCHES DRILLED VIAS | ( ) PEMNUTS TO BE INSTALLED BY FABRICATOR | ( ) PEMNUTS NOT TO BE INSTALLED BY FABRICATOR | (x) NOT APPLICABLE | USED AS VIA-IN-PAD OR AS A STACKED VIA. BLIND/BURIED VIAS WITH AN ASPECT RATIO >1:1 TO BE FILLED | A. UL CODE-FLAMMABILITY RATING FOR THOSE APPROVED MATERIALS(IF APPLICABLE) | B. DATE CODE | C. LOT NUMBER | D. MANUFACTURER LOGO | BOARDS TO BE SHIPPED IN ARRAY AND KEPT INTACT | PANEL TO BE SUBJECTED TO CUSTOMERS APPROVAL | PANEL SOLDER PASTE STENCIL GERBER TO BE PROVIDED TO ANALOG | CAN'T BE PERFORMED BECAUSE THE TRACE LENGTH IS TOO SHORT ON THE OUTER LAYERS AT THE PIN ESCAPES | ADI APPROVAL IS REQUIRED. | OF COMPLIANCE SHALL BE PROVIDED BY VENDOR AT TIME OF SHIPMENT. INSTANCES WHERE TDR TESTING | WITH NON-CONDUCTIVE EPOXY. | 2 | NOTES: | TOOLING: | FINISH: | MATERIAL: | TESTING: | MISCELLANEOUS:
User.11: 14
User.16: PER IPC-4552 LATEST REVISION | ENIG (Electroless Nickel/Immersion Gold)
User.18: 08-      -07 | L2-GND PLANE
User.19: 08-      -08 | L3-SIGNAL/GND
User.20: 08-      -09 | L4-SIGNAL/GND
User.21: L5-SIGNAL/GND | 08-      -10
User.26: IN | LED2 | LED1 | 2 | FOR I C | DC2026C | OPTIONAL | CONNECT TO | SHUTDOWN | ANALOG | CONNECT EN | TO GND FOR | DIMMING | CHANNEL2 | CHANNEL1 | 0V | SUPPLY | POWER | 1.5V | - | I | A | ALERT | FLAG | V | NON I C MODE | PWM DIMMING IN | FOR | SET ADDR1 & ADDR2 TO 00 | 6.8OHM | SET TO ANY OTHER VALUE FOR I C. | +
User.45: FIGURE | SIZE | 6.0 | 10.0 | 36.0 | 40.0 | 100.0 | PLATED | FINISHED HOLES IN MILS | ALL UNITS ARE IN MILS | QTY | 54 | 214 | 14 | TOLERANCE/NOTES
